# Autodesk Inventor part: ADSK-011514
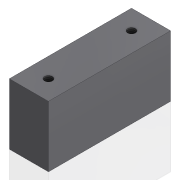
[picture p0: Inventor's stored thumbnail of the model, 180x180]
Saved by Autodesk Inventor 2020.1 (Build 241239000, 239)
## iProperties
Created: 1999-12
Part Number: ADSK-011514
Material: Acier doux
Document SubType Name: Modeling
Designer: sspink
Density: 7.86 g/cm^3
Appearance: Metal-Steel(Polish)
Mass: 155.627 g
Surface Area: 51.4312 cm^2
Volume: 19.7998 cm^3
Control State: 0
Master: False
Checked Out: False
Shininess: 0.0
Length Units: 11269
Angle Units: 11279
Time Units: 11290
Mass Units: 11283
Length Display Precision: 3
Angle Display Precision: 2
Compacted: True
Cutlength: 2
Material Desc: FLAT,HRS,0.625 X 1.00
Material_number: A084432
Dimensions: 16x25x50 mm
Mass: 0,156 kg
DocNumber: ADSK-011514.ipt
Folder: 01 - Themengebiete\Simplification\01 - Packaging machine\
VDS_Category: 3D Komponenten
Density: 0.0
Volumn: 0.0
Area: 0.0
PropertySet Name: Model Information
Author: sspink
Revision Number: -
Title: distance
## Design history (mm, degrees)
node "Solide1"
  node "Extrusion1" dims "d2" = 50, "d3" = 0
  node "Hole3" dims "d25" = 3.242, "d26" = 9.525, "d27" = 6.35, "d28" = 60 deg, "d29" = 11.8, "d30" = 118 deg, "d32" = 8
sketch "Sketch1"
  geometry: L1 (8, 12.5)-(-8, 12.5); L2 (-8, 12.5)-(-8, -12.5); L3 (-8, -12.5)-(8, -12.5); L4 (8, -12.5)-(8, 12.5); 3 further points
  constraints: 8 end point, 2 midpoint, 2 parallel, 1 horizontal, 1 horizontal alignment, 1 perpendicular, 1 vertical alignment
  dimensions: "d0" = 16 distance of L2.end L3.end; "d1" = 25 distance of L3.end L1.start
sketch "Sketch4"
  geometry: L1 (16, 0)-(0, 0) reference; L2 (0, 0)-(0, -50) reference; L3 (8, -8)-(8, -42); 3 further points
  constraints: 3 midpoint, 2 end point, 1 horizontal alignment, 1 vertical, 1 vertical alignment
  dimensions: "d31" = 34 distance of L3.start L3.end
node "Corps solides"
node "Corps surfaciques"
